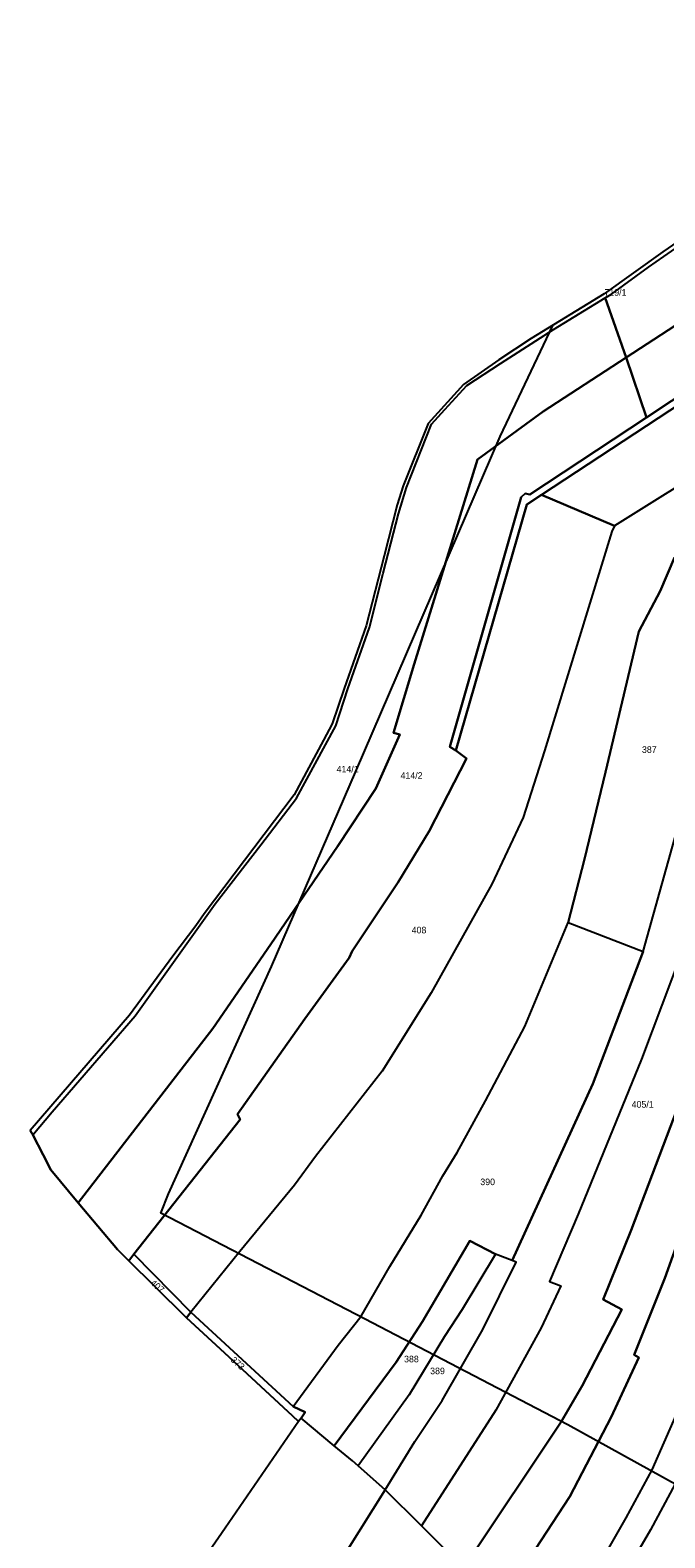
# Model space of a CAD drawing. Extents: x -629983 to -626385, y -1072828 to -1067897.
# Drawn here: x -629537 to -629248, y -1071334 to -1070647 of the extents above; entities that cross this region are included whole.
import ezdxf

# ---------------------------------------------------------------- set-up
doc = ezdxf.new("R2010")
doc.units = 0
for name, color, linetype in [('Cesty', 7, 'Continuous'), ('Parcela nároku', 7, 'Continuous'), ('Parcelní číslo', 7, 'Continuous'), ('Plocha PÚ', 7, 'Continuous'), ('Převzatý obvod_Ostrov', 7, 'Continuous')]:
    doc.layers.add(name, color=color, linetype=linetype)

msp = doc.modelspace()

# ---------------------------------------------------------------- linework, layer by layer
at = {"layer": 'Cesty'}
msp.add_lwpolyline([(-628936.41, -1071495.4), (-628984.66, -1071457.34), (-629028.63, -1071428.56), (-629097.8, -1071389.78), (-629291.66, -1071282.55), (-629384.37, -1071234.35), (-629477.09, -1071186.15), (-629473.61, -1071177.35), (-629426.68, -1071073.91), (-629388.47, -1070985.33), (-629322.56, -1070832.53), (-629298.49, -1070781.9)], dxfattribs=at)
at = {"layer": 'Parcela nároku'}
for points in [[(-629101.65, -1070659.15), (-629093.4, -1070655.06), (-629088.1, -1070653), (-629074.99, -1070647.48), (-629051.24, -1070672.45), (-629063.68, -1070676.94), (-629094.76, -1070689.87), (-629135.11, -1070709.94), (-629170.12, -1070732.01), (-629210.07, -1070761.98), (-629233.47, -1070775.9), (-629265.09, -1070796.47), (-629274.72, -1070769.42), (-629271.88, -1070767.69), (-629254.96, -1070755.46), (-629237.53, -1070743.22), (-629204.46, -1070719.83), (-629191.61, -1070710.9), (-629174.38, -1070698.47), (-629159.54, -1070688.21)], [(-629094.76, -1070689.87), (-629063.68, -1070676.94), (-629051.24, -1070672.45), (-629029.46, -1070695.49), (-629035.66, -1070697.66), (-629087.84, -1070718.12), (-629111.67, -1070729.62), (-629137.1, -1070741.07), (-629160.38, -1070753.87), (-629175.26, -1070763.77), (-629189.77, -1070774.71), (-629200.54, -1070787.31), (-629255.88, -1070823.88), (-629265.09, -1070796.47), (-629233.47, -1070775.9), (-629210.07, -1070761.98), (-629170.12, -1070732.01), (-629135.11, -1070709.94)], [(-629375.8, -1070894.7), (-629368.88, -1070867.74), (-629365.23, -1070855.8), (-629353.8, -1070826.88), (-629347.77, -1070820.18), (-629337.65, -1070809.34), (-629322.3, -1070799.29), (-629298.22, -1070783.77), (-629274.72, -1070769.42), (-629265.09, -1070796.47), (-629302.99, -1070821.12), (-629332.91, -1070842.97), (-629361.69, -1070936.16), (-629371.14, -1070967.45), (-629368.29, -1070968.25), (-629379.18, -1070992.87), (-629396.69, -1071019.25), (-629427.04, -1071063.66), (-629453.34, -1071102.11), (-629514.77, -1071181.4), (-629527.26, -1071166.41), (-629530.75, -1071159.56), (-629535.37, -1071150.49), (-629526.56, -1071140.01), (-629488.8, -1071096.26), (-629452.28, -1071045.29), (-629431.47, -1071018.48), (-629415.22, -1070997.24), (-629397.41, -1070964.3), (-629391.88, -1070947.41), (-629382.1, -1070919.49)], [(-629197.39, -1070789.31), (-629173.04, -1070812.3), (-629270.52, -1070873.17), (-629303.76, -1070859.01)], [(-629302.99, -1070821.12), (-629265.09, -1070796.47), (-629255.88, -1070823.88), (-629308.99, -1070858.96), (-629311.21, -1070858.43), (-629312.92, -1070860.17), (-629345.44, -1070973.87), (-629342.69, -1070975.46), (-629337.86, -1070979.11), (-629354.87, -1071012.16), (-629369.01, -1071035.48), (-629389.89, -1071066.84), (-629391.35, -1071069.98), (-629411.53, -1071097.68), (-629442.13, -1071141.07), (-629441.01, -1071143.56), (-629489.4, -1071204.87), (-629491.73, -1071207.82), (-629496.87, -1071202.68), (-629514.77, -1071181.4), (-629453.34, -1071102.11), (-629427.04, -1071063.66), (-629396.69, -1071019.25), (-629379.18, -1070992.87), (-629368.29, -1070968.25), (-629371.14, -1070967.45), (-629361.69, -1070936.16), (-629332.91, -1070842.97)], [(-629310.39, -1070863.41), (-629303.76, -1070859.01), (-629270.52, -1070873.17), (-629271.6, -1070875.84), (-629302.35, -1070975.62), (-629312.09, -1071006.02), (-629326.35, -1071036.44), (-629353.93, -1071085.89), (-629376.27, -1071121.48), (-629406.68, -1071160.36), (-629416.15, -1071173.43), (-629441.05, -1071203.68), (-629463.4, -1071231.3), (-629489.4, -1071204.87), (-629441.01, -1071143.56), (-629442.13, -1071141.07), (-629411.53, -1071097.68), (-629391.35, -1071069.98), (-629389.89, -1071066.84), (-629369.01, -1071035.48), (-629354.87, -1071012.16), (-629337.86, -1070979.11), (-629342.69, -1070975.46)], [(-629243.05, -1070887.54), (-629249.69, -1070902.97), (-629259.41, -1070921.33), (-629274.51, -1070985.43), (-629284.16, -1071024.99), (-629291.51, -1071053.87), (-629257.36, -1071066.95), (-629218.07, -1070926.35), (-629201.11, -1070928.03), (-629173.63, -1070913.37), (-629183.91, -1070877.02), (-629184.9, -1070874.26), (-629224.26, -1070895.2)], [(-629294.85, -1071219.25), (-629303.85, -1071238.44), (-629324.52, -1071275.85), (-629358.36, -1071328.63), (-629347.5, -1071339.42), (-629338.48, -1071349.57), (-629337.96, -1071346.05), (-629294.79, -1071281.13), (-629285.17, -1071264.79), (-629267.15, -1071230.1), (-629275.62, -1071225.43), (-629262.93, -1071193.94), (-629238.65, -1071130.37), (-629229.69, -1071103.25), (-629220.42, -1071074.94), (-629206.16, -1071038.51), (-629177.01, -1070970.08), (-629170.42, -1070956.77), (-629190.93, -1070945.74), (-629208.26, -1070986.56), (-629239.55, -1071066.87), (-629258.21, -1071116.1), (-629286.97, -1071186.58), (-629300.05, -1071217.22)], [(-629329.21, -1071135.1), (-629311.28, -1071101.2), (-629291.51, -1071053.87), (-629257.36, -1071066.95), (-629280.35, -1071127.36), (-629317.02, -1071207.67), (-629324.61, -1071204.78), (-629336.35, -1071198.73), (-629357.94, -1071235.52), (-629369.9, -1071253.98), (-629398.21, -1071292.1), (-629413.19, -1071279.59), (-629411.36, -1071276.84), (-629416.86, -1071274.27), (-629396.29, -1071246.26), (-629385.84, -1071233.03), (-629372.85, -1071210.39), (-629358.49, -1071187.07), (-629348.7, -1071169.17), (-629342.06, -1071158.56)], [(-629369.9, -1071253.98), (-629357.94, -1071235.52), (-629336.35, -1071198.73), (-629324.61, -1071204.78), (-629339.8, -1071230.04), (-629347.92, -1071242.36), (-629363.95, -1071268.93), (-629387.27, -1071301.19), (-629389.8, -1071298.94), (-629398.21, -1071292.1)], [(-629479.94, -1071219.45), (-629491.73, -1071207.82), (-629489.4, -1071204.87), (-629463.4, -1071231.3), (-629465.42, -1071233.79)], [(-629347.92, -1071242.36), (-629363.95, -1071268.93), (-629387.27, -1071301.19), (-629374.96, -1071312.14), (-629361.38, -1071290.1), (-629349.01, -1071271.54), (-629330.38, -1071239.11), (-629315.19, -1071208.51), (-629317.02, -1071207.67), (-629324.61, -1071204.78), (-629339.8, -1071230.04)], [(-629417.11, -1071278.43), (-629448.02, -1071249.71), (-629465.42, -1071233.79), (-629463.4, -1071231.3), (-629416.86, -1071274.27), (-629411.36, -1071276.84), (-629413.19, -1071279.59), (-629414.35, -1071281)], [(-629254.03, -1071330.35), (-629272.83, -1071362.67), (-629290.35, -1071392.92), (-629265.58, -1071400.87), (-629252.25, -1071376.87), (-629224.56, -1071326.33), (-629205.05, -1071279.48), (-629196.24, -1071250.14), (-629213.99, -1071243.83), (-629228.28, -1071278.52), (-629242.88, -1071309.5)], [(-629398.21, -1071292.1), (-629413.19, -1071279.59), (-629414.35, -1071281), (-629447.85, -1071329.61), (-629474.53, -1071368.28), (-629504.23, -1071411.99), (-629525.25, -1071443.82), (-629499.86, -1071501.13), (-629464.21, -1071453.03), (-629435.8, -1071407.84), (-629398.07, -1071349.14), (-629374.96, -1071312.14), (-629387.27, -1071301.19), (-629389.8, -1071298.94)], [(-629374.96, -1071312.14), (-629398.07, -1071349.14), (-629435.8, -1071407.84), (-629402.75, -1071431.14), (-629375.5, -1071385.29), (-629347.5, -1071339.42), (-629358.36, -1071328.63)]]:
    msp.add_lwpolyline(points, close=True, dxfattribs=at)
for points in [[(-629237.26, -1070740.64), (-629248.44, -1070748.49), (-629275.17, -1070767.57), (-629308.34, -1070787.94), (-629323.08, -1070797.6), (-629339.2, -1070808.89), (-629355.34, -1070826.55), (-629366.75, -1070854.95), (-629369.44, -1070863.68), (-629375.4, -1070886.86), (-629383.52, -1070918.68), (-629393.56, -1070947.2), (-629399.04, -1070963.33), (-629403.07, -1070970.73), (-629416.33, -1070995.69), (-629457.36, -1071049.84), (-629461.21, -1071055.33), (-629471.59, -1071069.16), (-629491.33, -1071096), (-629536.62, -1071148.52), (-629535.37, -1071150.49), (-629526.56, -1071140.01), (-629488.8, -1071096.26), (-629452.28, -1071045.29), (-629431.47, -1071018.48), (-629415.22, -1070997.24), (-629397.41, -1070964.3), (-629391.88, -1070947.41), (-629382.1, -1070919.49), (-629375.8, -1070894.7), (-629368.88, -1070867.74), (-629365.23, -1070855.8), (-629353.8, -1070826.88), (-629347.77, -1070820.18), (-629337.65, -1070809.34), (-629322.3, -1070799.29), (-629298.22, -1070783.77), (-629274.72, -1070769.42), (-629271.88, -1070767.69), (-629254.96, -1070755.46), (-629237.53, -1070743.22)], [(-629197.39, -1070789.31), (-629303.76, -1070859.01), (-629310.39, -1070863.41), (-629342.69, -1070975.46), (-629345.44, -1070973.87), (-629312.92, -1070860.17), (-629311.21, -1070858.43), (-629308.99, -1070858.96), (-629255.88, -1070823.88), (-629200.54, -1070787.31)], [(-629173.04, -1070812.3), (-629270.52, -1070873.17), (-629271.6, -1070875.84), (-629302.35, -1070975.62), (-629312.09, -1071006.02), (-629326.35, -1071036.44), (-629353.93, -1071085.89), (-629376.27, -1071121.48), (-629406.68, -1071160.36), (-629416.15, -1071173.43), (-629441.05, -1071203.68), (-629463.4, -1071231.3), (-629416.86, -1071274.27), (-629396.29, -1071246.26), (-629385.84, -1071233.03), (-629372.85, -1071210.39), (-629358.49, -1071187.07), (-629348.7, -1071169.17), (-629342.06, -1071158.56), (-629329.21, -1071135.1), (-629311.28, -1071101.2), (-629291.51, -1071053.87), (-629284.16, -1071024.99), (-629274.51, -1070985.43), (-629259.41, -1070921.33), (-629249.69, -1070902.97), (-629243.05, -1070887.54)], [(-629239.55, -1071066.87), (-629258.21, -1071116.1), (-629286.97, -1071186.58), (-629300.05, -1071217.22), (-629294.85, -1071219.25), (-629303.85, -1071238.44), (-629324.52, -1071275.85), (-629358.36, -1071328.63), (-629374.96, -1071312.14), (-629361.38, -1071290.1), (-629349.01, -1071271.54), (-629330.38, -1071239.11), (-629315.19, -1071208.51), (-629317.02, -1071207.67), (-629280.35, -1071127.36), (-629257.36, -1071066.95), (-629218.07, -1070926.35)], [(-629238.65, -1071130.37), (-629262.93, -1071193.94), (-629275.62, -1071225.43), (-629267.15, -1071230.1), (-629285.17, -1071264.79), (-629294.79, -1071281.13), (-629337.96, -1071346.05), (-629338.48, -1071349.57), (-629334.53, -1071354.01), (-629323.75, -1071366.72), (-629316.94, -1071355.08), (-629290.75, -1071315.24), (-629271.98, -1071279.14), (-629259.33, -1071251.95), (-629261.52, -1071250.75), (-629247.58, -1071215.85), (-629216.13, -1071127.98)], [(-629216.13, -1071127.98), (-629247.58, -1071215.85), (-629261.52, -1071250.75), (-629259.33, -1071251.95), (-629271.98, -1071279.14), (-629290.75, -1071315.24), (-629316.94, -1071355.08), (-629323.75, -1071366.72), (-629317.04, -1071373.47), (-629307.95, -1071381.69), (-629301.82, -1071386.8), (-629283.16, -1071356.41), (-629265.14, -1071324.98), (-629253.34, -1071302.99), (-629242.37, -1071278.1)], [(-629242.88, -1071309.5), (-629254.03, -1071330.35), (-629272.83, -1071362.67), (-629290.35, -1071392.92), (-629301.82, -1071386.8), (-629283.16, -1071356.41), (-629265.14, -1071324.98), (-629253.34, -1071302.99), (-629242.37, -1071278.1)]]:
    msp.add_lwpolyline(points, dxfattribs=at)
at = {"layer": 'Plocha PÚ'}
for points in [[(-629237.26, -1070740.64), (-629248.44, -1070748.49), (-629275.17, -1070767.57), (-629308.34, -1070787.94), (-629323.08, -1070797.6), (-629339.2, -1070808.89), (-629355.34, -1070826.55), (-629366.75, -1070854.95), (-629369.44, -1070863.68), (-629375.4, -1070886.86), (-629383.52, -1070918.68), (-629393.56, -1070947.2), (-629399.04, -1070963.33), (-629403.07, -1070970.73), (-629416.33, -1070995.69), (-629457.36, -1071049.84), (-629461.21, -1071055.33), (-629471.59, -1071069.16)], [(-629471.59, -1071069.16), (-629491.33, -1071096), (-629536.62, -1071148.52), (-629535.37, -1071150.49), (-629530.75, -1071159.56), (-629527.26, -1071166.41), (-629514.77, -1071181.4), (-629496.87, -1071202.68), (-629491.73, -1071207.82), (-629479.94, -1071219.45), (-629465.42, -1071233.79), (-629448.02, -1071249.71), (-629417.11, -1071278.43), (-629414.35, -1071281), (-629447.85, -1071329.61), (-629474.53, -1071368.28)]]:
    msp.add_lwpolyline(points, dxfattribs=at)
at = {"layer": 'Převzatý obvod_Ostrov'}
msp.add_lwpolyline([(-629237.26, -1070740.64), (-629248.44, -1070748.49), (-629275.17, -1070767.57), (-629308.34, -1070787.94), (-629323.08, -1070797.6), (-629339.2, -1070808.89), (-629355.34, -1070826.55), (-629366.75, -1070854.95), (-629369.44, -1070863.68), (-629375.4, -1070886.86), (-629383.52, -1070918.68), (-629393.56, -1070947.2), (-629399.04, -1070963.33), (-629403.07, -1070970.73), (-629416.33, -1070995.69), (-629457.36, -1071049.84), (-629461.21, -1071055.33), (-629471.59, -1071069.16), (-629491.33, -1071096), (-629536.62, -1071148.52), (-629535.37, -1071150.49), (-629530.75, -1071159.56), (-629527.26, -1071166.41), (-629514.77, -1071181.4), (-629496.87, -1071202.68), (-629491.73, -1071207.82), (-629479.94, -1071219.45), (-629465.42, -1071233.79), (-629448.02, -1071249.71), (-629417.11, -1071278.43), (-629414.35, -1071281), (-629447.85, -1071329.61), (-629474.53, -1071368.28)], dxfattribs=at)

# ---------------------------------------------------------------- texts
at = {"layer": 'Parcelní číslo'}
for s, p in [('719/1', (-629275.03, -1070768.41)), ('387', (-629257.94, -1070976.58)), ('414/1', (-629397.03, -1070985.5)), ('414/2', (-629367.9, -1070988.38)), ('408', (-629362.83, -1071058.77)), ('405/1', (-629262.64, -1071138.14)), ('390', (-629331.57, -1071173.42)), ('388', (-629366.3, -1071254.1)), ('389', (-629354.41, -1071259.51))]:
    msp.add_text(s, height=3, dxfattribs=at).set_placement(p)
for s, rotation, p in [('407', 319.34934, (-629482.15, -1071218.38)), ('373', 318.294, (-629445.54, -1071253.4))]:
    msp.add_text(s, height=3, rotation=rotation, dxfattribs=at).set_placement(p)

doc.saveas('drawing.dxf')
